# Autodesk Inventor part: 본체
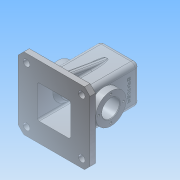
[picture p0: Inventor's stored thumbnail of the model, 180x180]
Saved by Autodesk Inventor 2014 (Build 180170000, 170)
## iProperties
Created: 2016-02
Part Number: 본체
Material: 알루미늄 6061
Document SubType Name: Modeling
Designer: net
Density: 2.71 g/cm^3
Appearance: 알루미늄 - 평지
Mass: 931.824 g
Surface Area: 1045.44 cm^2
Volume: 343.847 cm^3
Author: net
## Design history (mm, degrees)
sketch "스케치1"
  geometry: L1 (55, -65)-(-55, -65); L2 (-65, -55)-(-65, 55); L3 (-55, 65)-(55, 65); L4 (65, 55)-(65, -55); L5 (55, -65)-(65, -55); L6 (65, 55)-(55, 65); L7 (-55, 65)-(-65, 55); L8 (-65, -55)-(-55, -65); 5 further points
  constraints: 16 end point, 8 point on line, 2 parallel, 1 horizontal, 1 perpendicular
  dimensions: "d0" = 130 distance of point (65, -65) point (-65, -65); "d1" = 130 distance of point (-65, -65) point (-65, 65); "d2" = 65 distance from line of point (0, 0) L4; "d3" = 65 distance from line of point (0, 0) L1; "d4" = 10 distance of L1.start point (65, -65); "d5" = 10 distance of L4.end point (65, -65) (= d4); "d6" = 10 distance of L4.start point (65, 65) (= d4); "d7" = 10 distance of L3.end point (65, 65) (= d6); "d8" = 10 distance of L3.start point (-65, 65) (= d4); "d9" = 10 distance of L2.end point (-65, 65) (= d8); "d10" = 10 distance of L2.start point (-65, -65) (= d4); "d11" = 10 distance of L1.end point (-65, -65) (= d10)
extrude "돌출1" new body sketch "스케치1" distance "d12" = 10; taper "d13" = 0 deg
sketch "스케치2"
  geometry: L1 (-35, 35)-(35, 35); L2 (35, 35)-(35, -35); L3 (35, -35)-(-35, -35); L4 (-35, -35)-(-35, 35); 1 further point
  constraints: 8 end point, 2 parallel, 1 horizontal, 1 perpendicular
  dimensions: "d14" = 70 distance of L1.start L1.end; "d15" = 70 distance of L1.end L2.end; "d16" = 35 distance from line of point (0, 0) L1; "d17" = 35 distance from line of point (0, 0) L2
extrude "돌출2" join sketch "스케치2" distance "d18" = 110; taper "d19" = 0 deg
sketch "스케치3"
  geometry: L1 (0, 65)-(10, 65) reference; L2 (10, 65)-(10, 50); L3 (10, 50)-(95.069, 35); L4 (10, 35)-(120, 35) reference; L5 (10, 50)-(10, 35); L6 (10, 35)-(95.069, 35); L7 (10, -50)-(95.069, -35); L8 (10, -50)-(10, -35); L9 (10, -35)-(95.069, -35); L10 (120, -35)-(120, 35) reference; L11 (10, -35)-(120, -35) reference; L12 (-12.76, 30)-(115, 30); L13 (115, 30)-(115, -30); L14 (115, -30)-(-12.76, -30); L15 (-12.76, 30)-(-12.76, -30); 1 further point
  constraints: 22 end point, 3 perpendicular
  dimensions: "d20" = 15 distance of L1.end L2.end; "d21" = 10 deg angle of L1 L3; "d22" = 5 distance between parallel lines of L12 L4; "d23" = 5 distance between parallel lines of L10 L13; "d24" = 5 distance between parallel lines of L11 L14
extrude "돌출3" cut sketch "스케치3" stored distance "d25" = 60; taper "d26" = 0 deg
extrude "돌출4" join sketch "스케치3" stored distance "d27" = 10; taper "d28" = 0 deg
sketch "스케치4"
  geometry: L1 (0, 0)-(0, 55); L2 (0, 55)-(-48, 55); L3 (0, 55)-(48, 55)
  constraints: 6 end point, 1 collinear, 1 perpendicular, 1 vertical
  dimensions: "d29" = 55 distance of L1.start L1.end; "d30" = 48 distance of L1.end L2.end; "d31" = 48 distance of L1.end L3.end
node "작업 평면1"
node "작업 평면2"
sketch "스케치7"
  geometry: L1 (-30, 0)-(-30, 115) reference; L2 (0, 0)-(0, 55); C1 r 27.5 at (0, 55)
  constraints: 2 end point, 1 centre point, 1 coincident, 1 parallel
  dimensions: "d38" = 55 distance of L2.start L2.end; "d39" = 27.5 radius of C1
extrude "돌출7" join sketch "스케치7" distance "d40" = 7; taper "d41" = 0 deg
sketch "스케치8"
  geometry: L1 (-30, 0)-(-30, 115) reference; L2 (0, 0)-(0, 55); C1 r 27.5 at (0, 55)
  constraints: 2 end point, 1 centre point, 1 coincident, 1 parallel
  dimensions: "d42" = 55 distance of L2.start L2.end; "d43" = 27.5 radius of C1
extrude "돌출8" join sketch "스케치8" distance "d44" = 7; taper "d45" = 0 deg
feature "면 기울기1" dims angle "d46" = 45 deg
feature "면 기울기2" dims angle "d47" = 45 deg
sketch "스케치11"
  geometry: C1 r 20 at (0, 0); 1 further point
  constraints: 1 centre point, 1 coincident
  dimensions: "d95" = 20 radius of C1
extrude "돌출9" join sketch "스케치11" distance "d96" = 10; taper "d97" = 0 deg
feature "면 기울기3" dims angle "d98" = 10 deg
hole "구멍4" diameter "d101" = 21; stored, may be unused: countersink angle "d105" = 90 deg, drill point angle "d107" = 118 deg; dims "d99" = 10, "d100" = 10, "d102" = 6, "d103" = 28, "d104" = 4, "d106" = 10
hole "구멍5" diameter "d110" = 12; stored, may be unused: countersink angle "d114" = 90 deg, drill point angle "d116" = 118 deg; dims "d108" = 15, "d109" = 15, "d111" = 6, "d112" = 28, "d113" = 4, "d115" = 10
hole "구멍6" diameter "d119" = 12; stored, may be unused: countersink angle "d123" = 90 deg, drill point angle "d125" = 118 deg; dims "d117" = 15, "d118" = 15, "d120" = 6, "d121" = 28, "d122" = 4, "d124" = 10
hole "구멍7" diameter "d128" = 12; stored, may be unused: countersink angle "d132" = 90 deg, drill point angle "d134" = 118 deg; dims "d126" = 15, "d127" = 15, "d129" = 6, "d130" = 28, "d131" = 4, "d133" = 10
hole "구멍8" diameter "d137" = 12; stored, may be unused: countersink angle "d141" = 90 deg, drill point angle "d143" = 118 deg; dims "d135" = 15, "d136" = 15, "d138" = 6, "d139" = 28, "d140" = 4, "d142" = 10
fillet "모깎기2" dims "d145" = 3
fillet "모깎기3" dims "d146" = 3
fillet "모깎기4" dims "d147" = 0.5
fillet "모깎기7" dims "d153" = 8
fillet "모깎기8" dims "d154" = 8
sketch "스케치13"
  geometry: L1 (54, 102)-(54, 0) reference; L2 (27, -10)-(27, 45); C1 r 27.5 at (27, 45)
  constraints: 2 end point, 1 centre point, 1 coincident, 1 parallel
  dimensions: "d155" = 55 distance of L2.start L2.end; "d156" = 27.5 radius of C1
extrude "돌출10" join sketch "스케치13" distance "d157" = 13; taper "d158" = 0 deg
fillet "모깎기9" dims "d159" = 0.5
sketch "스케치14"
  geometry: L1 (54, 102)-(54, 0) reference; L2 (27, -10)-(27, 45); C1 r 27.5 at (27, 45)
  constraints: 2 end point, 1 centre point, 1 coincident, 1 parallel
  dimensions: "d160" = 55 distance of L2.start L2.end; "d161" = 27.5 radius of C1
extrude "돌출11" join sketch "스케치14" distance "d162" = 13; taper "d163" = 0 deg
fillet "모깎기10" dims "d164" = 0.5
hole "구멍9" diameter "d167" = 32; stored, may be unused: countersink angle "d171" = 90 deg, drill point angle "d173" = 118 deg; dims "d165" = 10, "d166" = 10, "d168" = 6, "d169" = 28, "d170" = 4, "d172" = 10
sketch "스케치15"
  geometry: L1 (0, 0)-(0, 22.5); C1 r 27.5 at (0, 0) reference; 1 further point
  constraints: 2 end point, 1 vertical
  dimensions: "d174" = 22.5 distance of L1.start L1.end
hole "구멍10" sketch "스케치15" at (0, 22.5) diameter "d175" = 4; stored, may be unused: countersink angle "d179" = 90 deg, drill point angle "d181" = 118 deg; dims "d176" = 6, "d177" = 28, "d178" = 4, "d180" = 10
sketch "스케치16"
  geometry: L1 (0, 0)-(0, 22.5); C1 r 27.5 at (0, 0) reference; 1 further point
  constraints: 2 end point, 1 vertical
  dimensions: "d182" = 22.5 distance of L1.start L1.end
hole "구멍11" sketch "스케치16" at (0, 22.5) diameter "d183" = 4; stored, may be unused: countersink angle "d187" = 90 deg, drill point angle "d189" = 118 deg; dims "d184" = 6, "d185" = 28, "d186" = 4, "d188" = 10
feature "스레드9" dims "d196" = 8, "d197" = 0
feature "스레드10" dims "d198" = 8, "d199" = 0
feature "스레드11" dims "d200" = 8, "d201" = 0
feature "스레드12" dims "d202" = 8, "d203" = 0
feature "스레드13" dims "d204" = 8, "d205" = 0
feature "스레드14" dims "d206" = 8, "d207" = 0
feature "스레드15" dims "d208" = 8, "d209" = 0
feature "스레드16" dims "d210" = 8, "d211" = 0
sketch "스케치17"
  geometry: L1 (45.237, 18)-(8.763, 18) reference; L2 (27, 18)-(27, -12); L3 (6.533, -8.675)-(48.012, -8.675); L4 (48.012, -8.675)-(48.012, -14.679); L5 (48.012, -14.679)-(6.533, -14.679); L6 (6.533, -14.679)-(6.533, -8.675); 1 further point
  constraints: 2 end point, 1 midpoint, 1 perpendicular, 2 other
  dimensions: "d212" = 30 distance of L2.start L2.end
feature "엠보싱2" sketch "스케치17" dims "d213" = 0.5, "d214" = 0
fillet "모깎기11" dims "d215" = 3
fillet "모깎기12" dims "d216" = 3
fillet "모깎기13" dims "d217" = 3
chamfer "모따기1" distance "d218" = 1; stored, may be unused: second distance "d219" = 2, angle "d220" = 45 deg
node "솔리드1"
pattern_circular "원형 패턴3" dims angle "d191" = 360 deg
pattern_circular "원형 패턴4" dims angle "d194" = 360 deg
